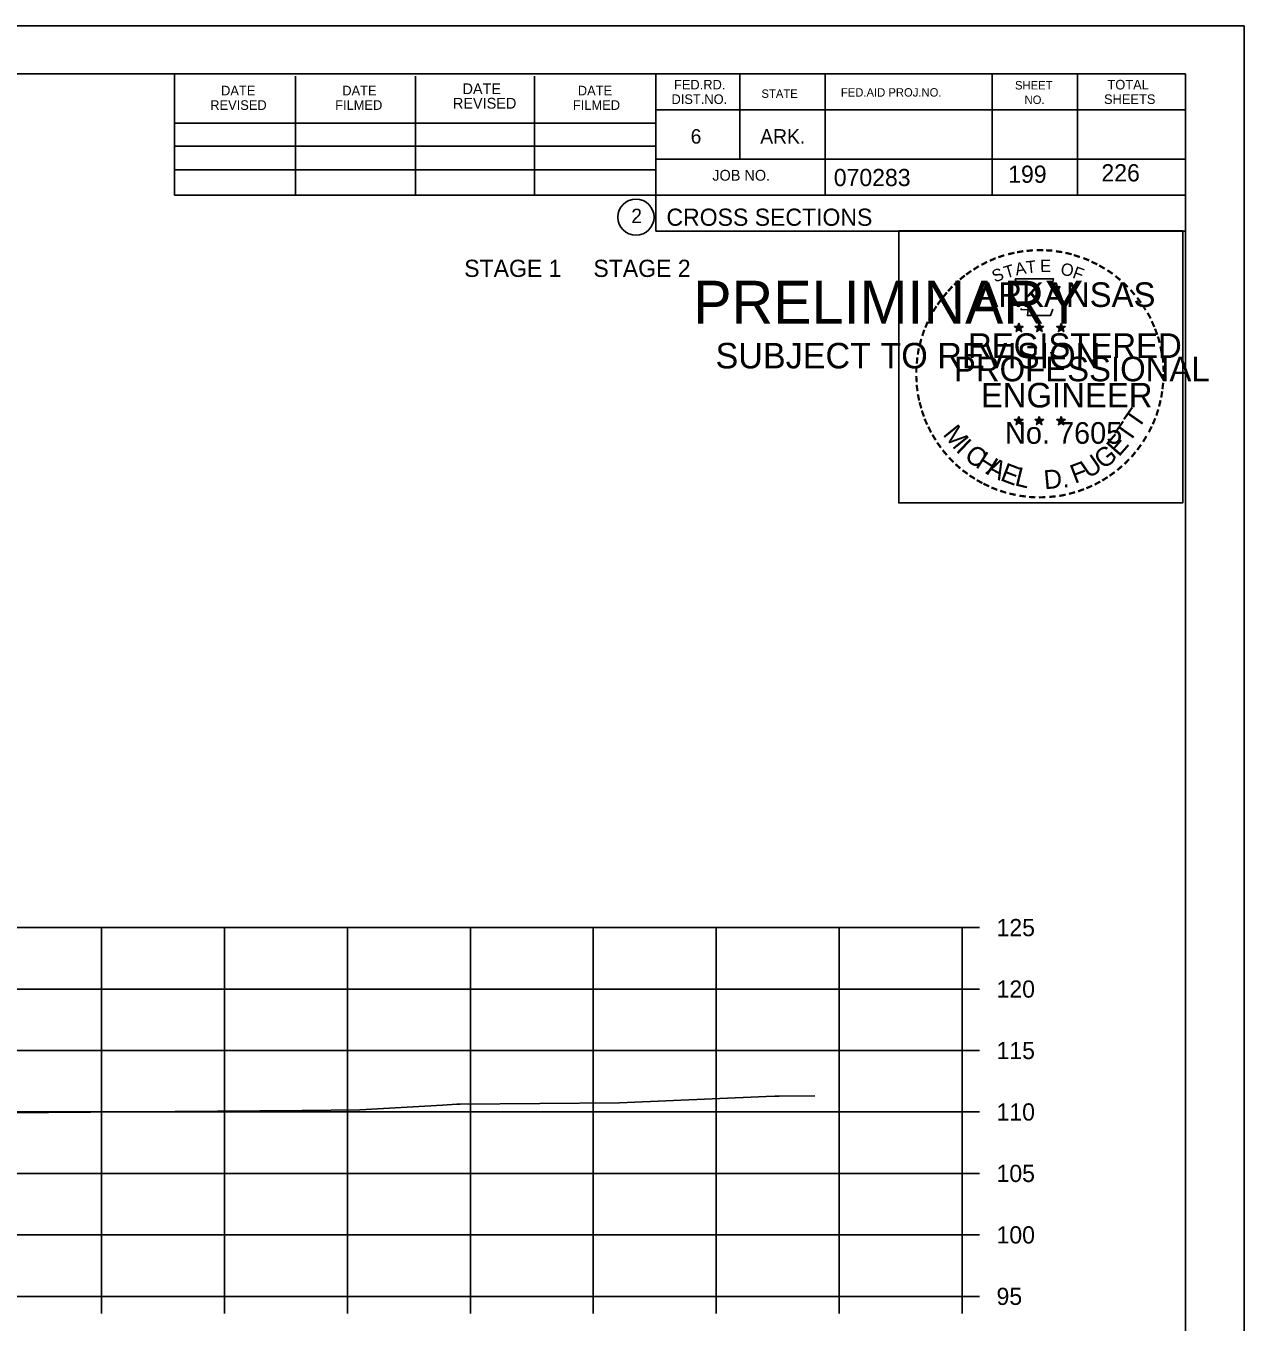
# Model space of a CAD drawing. Extents: x 1175611 to 1176402, y -433344 to -416213.
# Drawn here: x 1175844.8 to 1175943.9, y -422142.1 to -422036.6 of the extents above; entities that cross this region are included whole.
import ezdxf

# ---------------------------------------------------------------- set-up
doc = ezdxf.new("R2010")
doc.units = 0
for name, color, linetype in [('Default', 7, 'Continuous'), ('R_Axis', 7, 'Continuous'), ('R_Axis Annot', 7, 'Continuous'), ('R_Border', 7, 'Continuous'), ('R_Border Notes', 7, 'Continuous'), ('R_Border PE', 7, 'Continuous'), ('R_Border Prem', 7, 'Continuous'), ('R_Exist Surface', 7, 'Continuous'), ('R_Grid', 7, 'Continuous'), ('R_No Plot', 7, 'Continuous')]:
    doc.layers.add(name, color=color, linetype=linetype)

msp = doc.modelspace()

# ---------------------------------------------------------------- linework, layer by layer
at = {"layer": 'R_Axis'}
for p, q in [((1175920.97, -422139.97), (1175920.97, -422109.97)), ((1175922.37, -422109.97), (1175920.97, -422109.97)), ((1175922.37, -422114.97), (1175920.97, -422114.97)), ((1175922.37, -422119.97), (1175920.97, -422119.97)), ((1175922.37, -422124.97), (1175920.97, -422124.97)), ((1175922.37, -422129.97), (1175920.97, -422129.97)), ((1175922.37, -422134.97), (1175920.97, -422134.97)), ((1175640.97, -422139.97), (1175920.97, -422139.97)), ((1175850.97, -422141.37), (1175850.97, -422139.97)), ((1175860.97, -422141.37), (1175860.97, -422139.97)), ((1175870.97, -422141.37), (1175870.97, -422139.97)), ((1175880.97, -422141.37), (1175880.97, -422139.97)), ((1175890.97, -422141.37), (1175890.97, -422139.97)), ((1175900.97, -422141.37), (1175900.97, -422139.97)), ((1175910.97, -422141.37), (1175910.97, -422139.97)), ((1175920.97, -422141.37), (1175920.97, -422139.97)), ((1175922.37, -422139.97), (1175920.97, -422139.97))]:
    msp.add_line(p, q, dxfattribs=at)
at = {"layer": 'R_Border'}
for p, q in [((1175622.97, -422040.51), (1175939.15, -422040.51)), ((1175856.89, -422050.39), (1175856.89, -422040.51)), ((1175896.05, -422040.51), (1175896.05, -422053.31)), ((1175902.89, -422040.51), (1175902.89, -422047.45)), ((1175909.83, -422040.51), (1175909.83, -422050.39)), ((1175923.41, -422040.51), (1175923.41, -422050.39)), ((1175930.35, -422040.51), (1175930.35, -422050.39)), ((1175939.15, -422245.97), (1175939.15, -422040.51)), ((1175866.75, -422050.39), (1175866.75, -422040.71)), ((1175876.51, -422050.39), (1175876.51, -422040.71)), ((1175886.19, -422050.39), (1175886.19, -422040.71)), ((1175939.15, -422043.45), (1175896.05, -422043.45)), ((1175939.15, -422043.43), (1175939.15, -422043.43)), ((1175856.89, -422044.53), (1175896.05, -422044.53)), ((1175856.89, -422046.39), (1175896.05, -422046.39)), ((1175939.15, -422047.45), (1175896.05, -422047.45)), ((1175899.01, -422047.45), (1175939.15, -422047.45)), ((1175856.89, -422050.39), (1175856.89, -422048.33)), ((1175856.89, -422048.33), (1175896.05, -422048.33)), ((1175939.15, -422050.39), (1175856.89, -422050.39)), ((1175896.05, -422053.31), (1175939.15, -422053.31))]:
    msp.add_line(p, q, dxfattribs=at)
msp.add_circle((1175894.44, -422052.18), 1.47, dxfattribs=at)
at = {"layer": 'R_Border PE'}
for p, q in [((1175925.23, -422061.07), (1175925.58, -422061.18)), ((1175925.23, -422061.07), (1175925.49, -422061.11)), ((1175925.23, -422061.07), (1175925.47, -422061.19)), ((1175925.37, -422061.48), (1175925.58, -422061.18)), ((1175925.37, -422061.48), (1175925.49, -422061.23)), ((1175925.37, -422061.48), (1175925.58, -422061.26)), ((1175925.58, -422060.81), (1175925.54, -422061.07)), ((1175925.58, -422061.18), (1175925.58, -422060.81)), ((1175925.58, -422060.81), (1175925.63, -422061.06)), ((1175925.93, -422061.07), (1175925.58, -422061.18)), ((1175925.8, -422061.48), (1175925.58, -422061.18)), ((1175925.8, -422061.48), (1175925.58, -422061.26)), ((1175925.93, -422061.07), (1175925.64, -422061.12)), ((1175925.8, -422061.48), (1175925.66, -422061.18)), ((1175925.93, -422061.07), (1175925.73, -422061.17)), ((1175926.9, -422061.07), (1175927.25, -422061.18)), ((1175926.9, -422061.07), (1175927.16, -422061.11)), ((1175926.9, -422061.07), (1175927.14, -422061.19)), ((1175927.04, -422061.48), (1175927.25, -422061.18)), ((1175927.04, -422061.48), (1175927.16, -422061.23)), ((1175927.04, -422061.48), (1175927.25, -422061.26)), ((1175927.25, -422060.81), (1175927.21, -422061.07)), ((1175927.25, -422061.18), (1175927.25, -422060.81)), ((1175927.25, -422060.81), (1175927.3, -422061.06)), ((1175927.6, -422061.07), (1175927.25, -422061.18)), ((1175927.47, -422061.48), (1175927.25, -422061.18)), ((1175927.47, -422061.48), (1175927.25, -422061.26)), ((1175927.6, -422061.07), (1175927.31, -422061.12)), ((1175927.47, -422061.48), (1175927.33, -422061.18)), ((1175927.6, -422061.07), (1175927.4, -422061.17)), ((1175928.67, -422061.08), (1175929.02, -422061.19)), ((1175928.67, -422061.08), (1175928.92, -422061.12)), ((1175928.67, -422061.08), (1175928.91, -422061.2)), ((1175928.8, -422061.49), (1175929.02, -422061.19)), ((1175928.8, -422061.49), (1175928.93, -422061.24)), ((1175928.8, -422061.49), (1175929.02, -422061.27)), ((1175929.02, -422060.83), (1175928.98, -422061.08)), ((1175929.02, -422061.19), (1175929.02, -422060.83)), ((1175929.02, -422060.83), (1175929.07, -422061.08)), ((1175929.36, -422061.08), (1175929.02, -422061.19)), ((1175929.23, -422061.49), (1175929.02, -422061.19)), ((1175929.23, -422061.49), (1175929.02, -422061.27)), ((1175929.36, -422061.08), (1175929.08, -422061.13)), ((1175929.23, -422061.49), (1175929.09, -422061.2)), ((1175929.36, -422061.08), (1175929.16, -422061.18)), ((1175925.23, -422068.64), (1175925.58, -422068.75)), ((1175925.23, -422068.64), (1175925.48, -422068.69)), ((1175925.23, -422068.64), (1175925.47, -422068.76)), ((1175925.36, -422069.05), (1175925.58, -422068.75)), ((1175925.36, -422069.05), (1175925.49, -422068.8)), ((1175925.36, -422069.05), (1175925.58, -422068.83)), ((1175925.58, -422068.39), (1175925.54, -422068.64)), ((1175925.58, -422068.75), (1175925.58, -422068.39)), ((1175925.58, -422068.39), (1175925.63, -422068.64)), ((1175925.93, -422068.64), (1175925.58, -422068.75)), ((1175925.79, -422069.05), (1175925.58, -422068.75)), ((1175925.79, -422069.05), (1175925.58, -422068.83)), ((1175925.93, -422068.64), (1175925.64, -422068.69)), ((1175925.79, -422069.05), (1175925.66, -422068.76)), ((1175925.93, -422068.64), (1175925.72, -422068.74)), ((1175926.9, -422068.64), (1175927.25, -422068.75)), ((1175926.9, -422068.64), (1175927.15, -422068.69)), ((1175926.9, -422068.64), (1175927.14, -422068.76)), ((1175927.03, -422069.05), (1175927.25, -422068.75)), ((1175927.03, -422069.05), (1175927.16, -422068.8)), ((1175927.03, -422069.05), (1175927.25, -422068.83)), ((1175927.25, -422068.39), (1175927.21, -422068.64)), ((1175927.25, -422068.75), (1175927.25, -422068.39)), ((1175927.25, -422068.39), (1175927.3, -422068.64)), ((1175927.6, -422068.64), (1175927.25, -422068.75)), ((1175927.46, -422069.05), (1175927.25, -422068.75)), ((1175927.46, -422069.05), (1175927.25, -422068.83)), ((1175927.6, -422068.64), (1175927.31, -422068.69)), ((1175927.46, -422069.05), (1175927.32, -422068.76)), ((1175927.6, -422068.64), (1175927.39, -422068.74)), ((1175928.67, -422068.65), (1175929.02, -422068.76)), ((1175928.67, -422068.65), (1175928.92, -422068.7)), ((1175928.67, -422068.65), (1175928.9, -422068.77)), ((1175928.8, -422069.06), (1175929.02, -422068.76)), ((1175928.8, -422069.06), (1175928.93, -422068.81)), ((1175928.8, -422069.06), (1175929.01, -422068.84)), ((1175929.02, -422068.4), (1175928.97, -422068.65)), ((1175929.23, -422069.06), (1175929.01, -422068.84)), ((1175929.02, -422068.76), (1175929.02, -422068.4)), ((1175929.02, -422068.4), (1175929.06, -422068.65)), ((1175929.36, -422068.65), (1175929.02, -422068.76)), ((1175929.23, -422069.06), (1175929.02, -422068.76)), ((1175929.36, -422068.65), (1175929.08, -422068.7)), ((1175929.23, -422069.06), (1175929.09, -422068.77)), ((1175929.36, -422068.65), (1175929.16, -422068.75))]:
    msp.add_line(p, q, dxfattribs=at)
for points in [[(1175925.28, -422057.19), (1175925.54, -422058.02)], [(1175928.79, -422058.11), (1175928.93, -422057.83), (1175928.24, -422057.85), (1175928.39, -422057.19), (1175925.28, -422057.19)], [(1175925.77, -422059.61), (1175925.77, -422059.7), (1175926.33, -422059.72), (1175926.28, -422060.19), (1175928.15, -422060.19), (1175928.35, -422059.66)], [(1175925.58, -422060.81), (1175925.8, -422061.48), (1175925.23, -422061.07), (1175925.93, -422061.07), (1175925.37, -422061.48), (1175925.58, -422060.81)], [(1175927.25, -422060.81), (1175927.47, -422061.48), (1175926.9, -422061.07), (1175927.6, -422061.07), (1175927.04, -422061.48), (1175927.25, -422060.81)], [(1175929.02, -422060.83), (1175929.23, -422061.49), (1175928.67, -422061.08), (1175929.36, -422061.08), (1175928.8, -422061.49), (1175929.02, -422060.83)], [(1175925.58, -422068.39), (1175925.79, -422069.05), (1175925.23, -422068.64), (1175925.93, -422068.64), (1175925.36, -422069.05), (1175925.58, -422068.39)], [(1175927.25, -422068.39), (1175927.46, -422069.05), (1175926.9, -422068.64), (1175927.6, -422068.64), (1175927.03, -422069.05), (1175927.25, -422068.39)], [(1175929.02, -422068.4), (1175929.23, -422069.06), (1175928.67, -422068.65), (1175929.36, -422068.65), (1175928.8, -422069.06), (1175929.02, -422068.4)]]:
    msp.add_lwpolyline(points, dxfattribs=at)
for centre, radius in [((1175925.58, -422061.18), 0.172), ((1175925.58, -422061.18), 0.145), ((1175925.58, -422061.18), 0.116), ((1175925.58, -422061.18), 0.0991), ((1175925.58, -422061.18), 0.0747), ((1175925.58, -422061.18), 0.0495), ((1175925.58, -422061.18), 0.0296), ((1175927.25, -422061.18), 0.172), ((1175927.25, -422061.18), 0.145), ((1175927.25, -422061.18), 0.116), ((1175927.25, -422061.18), 0.0991), ((1175927.25, -422061.18), 0.0747), ((1175927.25, -422061.18), 0.0495), ((1175927.25, -422061.18), 0.0296), ((1175929.02, -422061.19), 0.172), ((1175929.02, -422061.19), 0.145), ((1175929.02, -422061.19), 0.116), ((1175929.02, -422061.19), 0.0991), ((1175929.02, -422061.19), 0.0747), ((1175929.02, -422061.19), 0.0495), ((1175929.02, -422061.19), 0.0296), ((1175925.58, -422068.75), 0.172), ((1175925.58, -422068.75), 0.145), ((1175925.58, -422068.75), 0.116), ((1175925.58, -422068.75), 0.0991), ((1175925.58, -422068.75), 0.0747), ((1175925.58, -422068.75), 0.0495), ((1175925.58, -422068.75), 0.0296), ((1175927.25, -422068.75), 0.172), ((1175927.25, -422068.75), 0.145), ((1175927.25, -422068.75), 0.116), ((1175927.25, -422068.75), 0.0991), ((1175927.25, -422068.75), 0.0747), ((1175927.25, -422068.75), 0.0495), ((1175927.25, -422068.75), 0.0296), ((1175929.01, -422068.76), 0.172), ((1175929.01, -422068.76), 0.145), ((1175929.01, -422068.76), 0.116), ((1175929.01, -422068.76), 0.0991), ((1175929.01, -422068.76), 0.0747), ((1175929.01, -422068.76), 0.0495), ((1175929.01, -422068.76), 0.0296)]:
    msp.add_circle(centre, radius, dxfattribs=at)
at = {"layer": 'R_Exist Surface'}
msp.add_lwpolyline([(1175832.84, -422125.13), (1175867.29, -422124.84), (1175871.99, -422124.79), (1175878.69, -422124.41), (1175879.88, -422124.34), (1175879.92, -422124.34), (1175880.14, -422124.34), (1175893.1, -422124.22), (1175905.04, -422123.7), (1175905.74, -422123.69), (1175906.08, -422123.68), (1175909, -422123.67)], dxfattribs=at)
at = {"layer": 'R_Grid'}
for p, q in [((1175640.97, -422109.97), (1175920.97, -422109.97)), ((1175850.97, -422139.97), (1175850.97, -422109.97)), ((1175860.97, -422139.97), (1175860.97, -422109.97)), ((1175870.97, -422139.97), (1175870.97, -422109.97)), ((1175880.97, -422139.97), (1175880.97, -422109.97)), ((1175890.97, -422139.97), (1175890.97, -422109.97)), ((1175900.97, -422139.97), (1175900.97, -422109.97)), ((1175910.97, -422139.97), (1175910.97, -422109.97)), ((1175920.97, -422139.97), (1175920.97, -422109.97)), ((1175640.97, -422114.97), (1175920.97, -422114.97)), ((1175640.97, -422119.97), (1175920.97, -422119.97)), ((1175640.97, -422124.97), (1175920.97, -422124.97)), ((1175640.97, -422129.97), (1175920.97, -422129.97)), ((1175640.97, -422134.97), (1175920.97, -422134.97)), ((1175640.97, -422139.97), (1175920.97, -422139.97))]:
    msp.add_line(p, q, dxfattribs=at)
at = {"layer": 'R_No Plot'}
msp.add_line((1175610.57, -422036.62), (1175943.91, -422036.62), dxfattribs=at)
for points in [[(1175610.57, -422036.62), (1175943.91, -422036.62), (1175943.91, -422249.96), (1175610.57, -422249.96)], [(1175915.82, -422053.28), (1175938.92, -422053.28), (1175938.92, -422075.43), (1175915.82, -422075.43)]]:
    msp.add_lwpolyline(points, close=True, dxfattribs=at)

# ---------------------------------------------------------------- texts
at = {"layer": 'Default'}
msp.add_text('STAGE 1     STAGE 2', height=1.4, dxfattribs=at).set_placement((1175880.47, -422057.04))
at = {"layer": 'R_Axis Annot'}
for s, p in [('125', (1175923.77, -422110.67)), ('120', (1175923.77, -422115.67)), ('115', (1175923.77, -422120.67)), ('110', (1175923.77, -422125.67)), ('105', (1175923.77, -422130.67)), ('100', (1175923.77, -422135.67)), ('95', (1175923.77, -422140.67))]:
    msp.add_text(s, height=1.4, dxfattribs=at).set_placement(p)
at = {"layer": 'R_Border'}
for s, height, p in [('DATE', 0.782, (1175860.69, -422042.27)), ('DATE', 0.782, (1175870.55, -422042.27)), ('DATE', 0.879, (1175880.33, -422042.17)), ('DATE', 0.782, (1175889.71, -422042.27)), ('FED.RD.', 0.782, (1175897.53, -422041.79)), ('SHEET', 0.684, (1175925.27, -422041.79)), ('TOTAL', 0.782, (1175932.79, -422041.79)), ('REVISED', 0.879, (1175879.55, -422043.35)), ('DIST.NO.', 0.782, (1175897.33, -422042.97)), ('STATE', 0.684, (1175904.65, -422042.47)), ('FED.AID PROJ.NO.', 0.684, (1175911.11, -422042.37)), ('NO.', 0.684, (1175926.05, -422042.97)), ('SHEETS', 0.782, (1175932.51, -422042.97)), ('REVISED', 0.782, (1175859.81, -422043.45)), ('FILMED', 0.782, (1175869.97, -422043.45)), ('FILMED', 0.782, (1175889.31, -422043.45)), ('6', 1.17, (1175898.89, -422046.19)), ('ARK.', 1.172, (1175904.55, -422046.19)), ('JOB NO.', 0.879, (1175900.65, -422049.21)), ('070283', 1.4, (1175910.53, -422049.65)), ('2', 1.17, (1175894.06, -422052.66)), ('CROSS SECTIONS', 1.4, (1175896.92, -422052.88))]:
    msp.add_text(s, height=height, rotation=360, dxfattribs=at).set_placement(p)
at = {"layer": 'R_Border Notes'}
for s, p in [('226', (1175932.3, -422049.27)), ('199', (1175924.72, -422049.38))]:
    msp.add_text(s, height=1.4, dxfattribs=at).set_placement(p)
at = {"layer": 'R_Border PE'}
for s, height, rotation, p in [('-', 1.6, 19.1761, (1175924.02, -422056.06)), ('-', 1.6, 13.6301, (1175924.77, -422055.82)), ('-', 1.6, 10.2193, (1175925.45, -422055.66)), ('-', 1.6, 5.8968, (1175926.18, -422055.55)), ('-', 1.6, 0.1862, (1175926.95, -422055.48)), ('-', 1.6, 357.743, (1175927.67, -422055.49)), ('-', 1.6, 352.1617, (1175928.42, -422055.55)), ('-', 1.6, 347.2049, (1175929.14, -422055.66)), ('-', 1.6, 342.3362, (1175929.77, -422055.82)), ('-', 1.6, 34.0636, (1175922.16, -422057.02)), ('-', 1.6, 28.7918, (1175922.76, -422056.65)), ('-', 1.6, 24.3072, (1175923.39, -422056.33)), ('T', 1, 16.4036, (1175924.54, -422057.18)), ('A', 1, 11.2132, (1175925.37, -422056.93)), ('T', 1, 6.0228, (1175926.22, -422056.76)), ('E', 1, 0.8323, (1175927.32, -422056.65)), ('O', 1, 350.4515, (1175928.93, -422056.86)), ('F', 1, 340.0707, (1175929.88, -422057.09)), ('-', 1.6, 337.8551, (1175930.51, -422056.04)), ('-', 1.6, 334.1211, (1175931.14, -422056.31)), ('-', 1.6, 329.6409, (1175931.72, -422056.59)), ('-', 1.6, 42.9622, (1175920.67, -422058.21)), ('-', 1.6, 38.9507, (1175921.1, -422057.79)), ('-', 1.6, 36.2317, (1175921.58, -422057.41)), ('S', 1, 21.594, (1175923.63, -422057.51)), ('-', 1.6, 325.8627, (1175932.36, -422056.95)), ('-', 1.6, 320.5297, (1175932.97, -422057.38)), ('-', 1.6, 50.6142, (1175919.82, -422059.17)), ('-', 1.6, 48.423, (1175920.22, -422058.69)), ('ARKANSAS', 2, 360, (1175922.13, -422059.48)), ('-', 1.6, 315.5786, (1175933.57, -422057.87)), ('-', 1.6, 309.8797, (1175934.14, -422058.42)), ('-', 1.6, 58.0706, (1175919.08, -422060.27)), ('-', 1.6, 54.2325, (1175919.41, -422059.74)), ('-', 1.6, 306.6522, (1175934.66, -422059.02)), ('-', 1.4, 303.6753, (1175935.15, -422059.59)), ('-', 1.6, 62.8713, (1175918.77, -422060.88)), ('-', 1.6, 299.6684, (1175935.47, -422060.19)), ('-', 1.6, 72.3945, (1175918.29, -422062.12)), ('-', 1.6, 67.7743, (1175918.51, -422061.49)), ('REGISTERED', 2, 360, (1175921.45, -422063.63)), ('DWB', 0.01, 360, (1175925.57, -422061.18)), ('DWB', 0.01, 360, (1175927.24, -422061.18)), ('DWB', 0.01, 360, (1175929, -422061.2)), ('-', 1.6, 294.6628, (1175935.79, -422060.81)), ('-', 1.6, 290.5728, (1175936.05, -422061.38)), ('-', 1.6, 75.461, (1175918.09, -422062.84)), ('-', 1.6, 285.1233, (1175936.28, -422061.96)), ('-', 1.6, 85.1863, (1175917.89, -422064.24)), ('-', 1.6, 81.2013, (1175917.96, -422063.55)), ('PROFESSIONAL', 2, 360, (1175920.3, -422065.53)), ('-', 1.6, 280.5493, (1175936.48, -422062.71)), ('-', 1.6, 276.5962, (1175936.65, -422063.47)), ('-', 1.6, 89.0622, (1175917.86, -422064.94)), ('-', 1.6, 274.3301, (1175936.71, -422064.2)), ('-', 1.6, 94.1959, (1175917.9, -422065.67)), ('-', 1.6, 98.9479, (1175917.97, -422066.33)), ('ENGINEER', 2, 360, (1175922.49, -422067.66)), ('-', 1.6, 263.5172, (1175936.72, -422065.49)), ('-', 1.6, 269.9407, (1175936.74, -422064.83)), ('-', 1.6, 101.7149, (1175918.1, -422067.07)), ('-', 1.6, 260.9953, (1175936.65, -422066.15)), ('-', 1.6, 105.4578, (1175918.27, -422067.66)), ('-', 1.6, 109.0874, (1175918.48, -422068.29)), ('T', 1.54, 55.055, (1175935.3, -422069.49)), ('-', 1.6, 252.8681, (1175936.36, -422067.55)), ('-', 1.6, 255.7626, (1175936.54, -422066.83)), ('-', 1.6, 114.0643, (1175918.73, -422068.89)), ('No. 7605', 1.757, 360, (1175924.46, -422070.61)), ('DWB', 0.01, 360, (1175925.56, -422068.76)), ('DWB', 0.01, 360, (1175927.23, -422068.76)), ('DWB', 0.01, 360, (1175929, -422068.77)), ('T', 1.54, 55.055, (1175934.57, -422070.61)), ('-', 1.6, 247.8887, (1175936.14, -422068.22)), ('-', 1.6, 115.7289, (1175919.04, -422069.51)), ('-', 1.6, 120.4471, (1175919.4, -422070.09)), ('M', 1.54, 308.9175, (1175919.35, -422069.86)), ('E', 1.54, 48.7313, (1175933.72, -422071.73)), ('-', 1.6, 239.0712, (1175935.48, -422069.6)), ('-', 1.6, 244.6197, (1175935.87, -422068.85)), ('-', 1.6, 125.8934, (1175919.8, -422070.65)), ('-', 1.6, 130.7181, (1175920.26, -422071.2)), ('I', 1.54, 316.4636, (1175920.39, -422071.18)), ('C', 1.54, 324.0197, (1175921.06, -422071.8)), ('G', 1.54, 38.2173, (1175932.47, -422072.75)), ('-', 1.6, 233.8452, (1175935.08, -422070.25)), ('-', 1.6, 134.2238, (1175920.78, -422071.75)), ('H', 1.54, 327.5342, (1175921.97, -422072.46)), ('A', 1.54, 332.5513, (1175922.83, -422073)), ('F', 1.54, 20.8202, (1175930.13, -422073.88)), ('U', 1.54, 34.4052, (1175931.27, -422073.49)), ('-', 1.6, 225.7653, (1175934.17, -422071.38)), ('-', 1.6, 231.2538, (1175934.65, -422070.82)), ('-', 1.6, 138.9338, (1175921.3, -422072.21)), ('-', 1.6, 144.6463, (1175921.86, -422072.62)), ('-', 1.6, 148.0898, (1175922.42, -422072.99)), ('E', 1.54, 339.2068, (1175923.99, -422073.56)), ('L', 1.54, 346.2929, (1175925.18, -422073.98)), ('D.', 1.54, 5.2602, (1175927.68, -422074.32)), ('-', 1.6, 215.7363, (1175933.1, -422072.36)), ('-', 1.6, 221.0851, (1175933.65, -422071.89)), ('-', 1.6, 151.5704, (1175923, -422073.32)), ('-', 1.6, 154.6002, (1175923.52, -422073.56)), ('-', 1.6, 158.5612, (1175924.15, -422073.82)), ('-', 1.6, 200.7184, (1175930.76, -422073.69)), ('-', 1.6, 204.2516, (1175931.38, -422073.42)), ('-', 1.6, 207.3568, (1175932.01, -422073.1)), ('-', 1.6, 212.2491, (1175932.56, -422072.75)), ('-', 1.6, 162.7983, (1175924.83, -422074.03)), ('-', 1.6, 167.5555, (1175925.55, -422074.19)), ('-', 1.6, 173.1155, (1175926.32, -422074.3)), ('-', 1.6, 176.5183, (1175927.07, -422074.36)), ('-', 1.6, 181.5918, (1175927.81, -422074.34)), ('-', 1.6, 185.8167, (1175928.62, -422074.26)), ('-', 1.6, 191.2858, (1175929.36, -422074.13)), ('-', 1.6, 195.4743, (1175930.09, -422073.93))]:
    msp.add_text(s, height=height, rotation=rotation, dxfattribs=at).set_placement(p)
at = {"layer": 'R_Border Prem'}
for s, height, p in [('PRELIMINARY', 3.5, (1175899.1, -422060.85)), ('DWB', 0.01, (1175899.85, -422059)), ('SUBJECT TO REVISION', 2.0751, (1175900.91, -422064.48))]:
    msp.add_text(s, height=height, rotation=360, dxfattribs=at).set_placement(p)

doc.saveas('drawing.dxf')
